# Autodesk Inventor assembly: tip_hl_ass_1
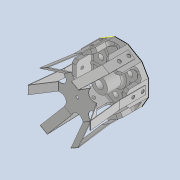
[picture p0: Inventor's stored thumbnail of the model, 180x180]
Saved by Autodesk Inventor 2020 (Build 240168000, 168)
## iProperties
Created: 2021-10
Part Number: tip_hl_ass_1
Document SubType Name: Assembly
Designer: Shuang Peng
Author: Shuang Peng
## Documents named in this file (6)
- D:\projects-3\torque fb tip\hardware\compact_ma_tmp\tip_hl_ass_1.iam
- D:\projects-3\torque fb tip\hardware\compact_ma_tmp\fin_12mm_h.ipt
- D:\projects-3\torque fb tip\hardware\compact_ma_tmp\fin_12mm.ipt
- D:\projects-3\torque fb tip\hardware\compact_ma_tmp\fin_8mm.ipt
- D:\projects-3\torque fb tip\hardware\compact_ma_tmp\mid_7mm.ipt
- D:\projects-3\torque fb tip\hardware\compact_ma_tmp\up_10mm_pr.ipt
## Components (20 placed, 5 different names)
1. fin_12mm_h:1 — Insert:11, Insert:29
2. fin_12mm_h:2 — Insert:12, Insert:28
3. fin_12mm_h:3 — Insert:7, Insert:27
4. fin_12mm_h:4 — Insert:10, Insert:30
5. fin_12mm_h:5 — Insert:9, Insert:26
6. fin_12mm_h:6 — Insert:8, Insert:25
7. fin_12mm:1 — Insert:8, Insert:14
8. fin_12mm:2 — Insert:9, Insert:15
9. fin_12mm:3 — Insert:10, Insert:16
10. fin_12mm:4 — Insert:12, Insert:18
11. fin_12mm:5 — Insert:11, Insert:17
12. fin_12mm:6 — Insert:7, Insert:13
13. fin_8mm:1 — Insert:13, Insert:22
14. fin_8mm:2 — Insert:15, Insert:24
15. fin_8mm:3 — Insert:14, Insert:21
16. fin_8mm:4 — Insert:18, Insert:23
17. fin_8mm:5 — Insert:16, Insert:20
18. fin_8mm:6 — Insert:17, Insert:19
19. mid_7mm:1 — Insert:19, Insert:20, Insert:21, Insert:22, Insert:23, Insert:24
20. up_10mm_pr:1 — Insert:25, Insert:26, Insert:27, Insert:28, Insert:29, Insert:30
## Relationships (24: Insert 24)
- Insert:7: fin_12mm_h:3 ↔ fin_12mm:6
- Insert:8: fin_12mm_h:6 ↔ fin_12mm:1
- Insert:9: fin_12mm_h:5 ↔ fin_12mm:2
- Insert:10: fin_12mm_h:4 ↔ fin_12mm:3
- Insert:11: fin_12mm_h:1 ↔ fin_12mm:5
- Insert:12: fin_12mm_h:2 ↔ fin_12mm:4
- Insert:13: fin_12mm:6 ↔ fin_8mm:1
- Insert:14: fin_12mm:1 ↔ fin_8mm:3
- Insert:15: fin_12mm:2 ↔ fin_8mm:2
- Insert:16: fin_12mm:3 ↔ fin_8mm:5
- Insert:17: fin_12mm:5 ↔ fin_8mm:6
- Insert:18: fin_12mm:4 ↔ fin_8mm:4
- Insert:19: fin_8mm:6 ↔ mid_7mm:1
- Insert:20: fin_8mm:5 ↔ mid_7mm:1
- Insert:21: fin_8mm:3 ↔ mid_7mm:1
- Insert:22: fin_8mm:1 ↔ mid_7mm:1
- Insert:23: fin_8mm:4 ↔ mid_7mm:1
- Insert:24: fin_8mm:2 ↔ mid_7mm:1
- Insert:25: fin_12mm_h:6 ↔ up_10mm_pr:1
- Insert:26: fin_12mm_h:5 ↔ up_10mm_pr:1
- Insert:27: fin_12mm_h:3 ↔ up_10mm_pr:1
- Insert:28: fin_12mm_h:2 ↔ up_10mm_pr:1
- Insert:29: fin_12mm_h:1 ↔ up_10mm_pr:1
- Insert:30: fin_12mm_h:4 ↔ up_10mm_pr:1
